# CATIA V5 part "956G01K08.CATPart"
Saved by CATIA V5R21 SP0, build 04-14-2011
Part number: 956G01K08
Bounding box of the stored display mesh (mm): x -33.75 to 33.05, y -127.5 to 127.5, z -8 to 12
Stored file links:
  C:\Users\ALI OZGUN\Desktop\alhan\TESLIMEDILEN3\956G01K08.CATPart
  C:\Users\ALI OZGUN\Desktop\alhan\TESLIMEDILEN3\960B01P01.CATPart
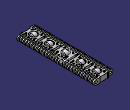
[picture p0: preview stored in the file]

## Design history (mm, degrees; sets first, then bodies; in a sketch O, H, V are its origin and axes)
Set1
  Plane1: type Normal, Curve Sketch6, RefPoint Sketch6.P3
Body1 (main body)
  Sketch1 on zx-plane, origin (0, 0, 0), H (-1, 0, 0), V (0, 0, 1)
    construction line L1 (-25.05, 0) -> (25.75, 0)
    point P1 (-25.05, 0)
    line L2 (-25.05, 8) -> (25.75, 8)
    line L3 (25.75, -8) -> (-25.05, -8)
    arc A1 centre (25.75, 0) radius 8 from (25.75, 8) to (25.75, -8) cw
    arc A2 centre (-25.05, 0) radius 8 from (-25.05, -8) to (-25.05, 8) cw
    distance L1 L2 = 8
    distance P1 V = 25.05
    length L1 = 50.8
    coincidence: P1 H
    horizontal: L1 H
    tangency: A1 L2, A2 L2, A1 L3, A2 L3
  Pad1: profile Sketch1, direction (0, 1, 0), length 127.5, mirrored extent
  Sketch2 on face of Pad1 from Sketch1.L2, origin (0, 0, 8), H (1, 0, 0), V (0, 1, 0)
    line L1 (-50.9731, -119.3) -> (-16.75, -119.3)
    line L2 (-15.75, -120.3) -> (-15.75, -122.5)
    line L3 (-16.75, -123.5) -> (-50.9731, -123.5)
    line L4 (-50.9731, -123.5) -> (-50.9731, -119.3)
    arc A1 centre (-16.75, -120.3) radius 1 from (-16.75, -119.3) to (-15.75, -120.3) cw
    arc A2 centre (-16.75, -122.5) radius 1 from (-15.75, -122.5) to (-16.75, -123.5) cw
    reference projected line E1 (-25.75, -127.5) -> (25.05, -127.5) from edge [start face of Pad1 | face of Pad1 from Sketch1.L2]
    reference projected line E2 through (-25.75, 0) direction (0, 1) from axis of face of Pad1 from Sketch1.A1
    radius A1 = 1
    radius A2 = 1 {= Sketch2.radius(A1)}
    length L4 = 4.2
    distance L3 E1 = 4
    distance L2 E2 = 10
    horizontal: L1 H, L3 H
    vertical: L2 V, L4 V
    tangency: A1 L1, A1 L2, A2 L2, A2 L3
  Pocket1: profile Sketch2, direction (0, 0, -1), length 30, mirrored extent
  RectPattern1: of Pocket1, direction 1 instances 32, spacing 8.2, along axis of face of Pad1 from Sketch1.A1
  Sketch3 on face of Pad1 from Sketch1.L2, origin (0, 0, 8), H (1, 0, 0), V (0, 1, 0)
    line L1 (50.2731, -123.4) -> (50.2731, -127.6)
    line L2 (50.2731, -127.6) -> (16.05, -127.6)
    arc A1 centre (16.0504, -126.5996) radius 1.0004 from (16.05, -127.6) to (15.05, -126.6) cw
    line L3 (15.05, -126.6) -> (15.05, -124.4)
    arc A2 centre (16.0504, -124.4004) radius 1.0004 from (15.05, -124.4) to (16.05, -123.4) cw
    line L4 (16.05, -123.4) -> (50.2731, -123.4)
    reference projected line E2 through (25.05, 0) direction (0, 1) from axis of face of Pad1 from Sketch1.A2
    reference projected line E3 (-25.75, -127.5) -> (25.05, -127.5) from edge [start face of Pad1 | face of Pad1 from Sketch1.L2]
    distance L3 E2 = 10
    distance L4 E3 = 4.1
  Pocket2: profile Sketch3, direction (0, 0, -1), length 30
  RectPattern2: of Pocket2, direction 1 instances 32, spacing 8.2, along axis of face of Pad1 from Sketch1.A2
  RemoveFace1: RemoveFaces (face of RectPattern2; face of RectPattern2)
  RemoveFace2: RemoveFaces (face of RectPattern1; face of RectPattern1; face of Pad1 from Sketch1.A1)
  Sketch4 on face of Pad1 from Sketch1.L2, origin (0, 0, 8), H (1, 0, 0), V (0, 1, 0)
    circle A1 centre (0, -101.5) radius 12
    point P1 (0, -101.5)
    point P2 (-13, -84.5)
    line L1 (-12, -84.5) -> (-7.7574, -84.5)
    line L2 (13, -85.5) -> (13, -89.7426)
    line L3 (-7.7574, -118.5) -> (-12, -118.5)
    line L4 (-13, -117.5) -> (-13, -113.2574)
    point P3 (13, -84.5)
    point P4 (13, -118.5)
    point P5 (-13, -118.5)
    reference projected line E1 (-25.75, -127.5) -> (25.05, -127.5) from edge [start face of Pad1 | face of Pad1 from Sketch1.L2]
    line L5 (7.0503, -86.2071) -> (11.2929, -90.4497)
    line L6 (-7.0503, -86.2071) -> (-11.2929, -90.4497)
    line L7 (-11.2929, -112.5503) -> (-7.0503, -116.7929)
    line L8 (7.0503, -116.7929) -> (11.2929, -112.5503)
    arc A2 centre (12, -117.5) radius 1 from (12, -118.5) to (13, -117.5) ccw
    point P6 (12, -118.5)
    arc A3 centre (-12, -117.5) radius 1 from (-12, -118.5) to (-13, -117.5) cw
    arc A4 centre (-12, -85.5) radius 1 from (-12, -84.5) to (-13, -85.5) ccw
    arc A5 centre (12, -85.5) radius 1 from (12, -84.5) to (13, -85.5) cw
    line L9 (13, -113.2574) -> (13, -117.5)
    line L10 (7.7574, -84.5) -> (12, -84.5)
    line L11 (-13, -89.7426) -> (-13, -85.5)
    line L12 (12, -118.5) -> (7.7574, -118.5)
    arc A6 centre (12, -113.2574) radius 1 from (13, -113.2574) to (11.2929, -112.5503) ccw
    arc A7 centre (7.7574, -85.5) radius 1 from (7.7574, -84.5) to (7.0503, -86.2071) ccw
    arc A8 centre (12, -89.7426) radius 1 from (11.2929, -90.4497) to (13, -89.7426) ccw
    arc A9 centre (-7.7574, -85.5) radius 1 from (-7.7574, -84.5) to (-7.0503, -86.2071) cw
    arc A10 centre (-12, -89.7426) radius 1 from (-13, -89.7426) to (-11.2929, -90.4497) ccw
    arc A11 centre (-12, -113.2574) radius 1 from (-13, -113.2574) to (-11.2929, -112.5503) cw
    arc A12 centre (-7.7574, -117.5) radius 1 from (-7.0503, -116.7929) to (-7.7574, -118.5) cw
    arc A13 centre (7.7574, -117.5) radius 1 from (7.7574, -118.5) to (7.0503, -116.7929) cw
    point P42 (-13, -72.3)
    line L13 (-12, -72.3) -> (12, -72.3)
    line L14 (13, -73.3) -> (13, -78.3)
    line L15 (12, -79.3) -> (-12, -79.3)
    line L16 (-13, -78.3) -> (-13, -73.3)
    point P43 (13, -79.3)
    point P44 (-13, -79.3)
    arc A14 centre (-12, -73.3) radius 1 from (-12, -72.3) to (-13, -73.3) ccw
    point P45 (-12, -72.3)
    point P46 (-13, -73.3)
    arc A15 centre (12, -73.3) radius 1 from (12, -72.3) to (13, -73.3) cw
    point P48 (12, -72.3)
    point P49 (13, -73.3)
    arc A16 centre (12, -78.3) radius 1 from (13, -78.3) to (12, -79.3) cw
    point P51 (13, -78.3)
    point P52 (12, -79.3)
    arc A17 centre (-12, -78.3) radius 1 from (-12, -79.3) to (-13, -78.3) cw
    point P54 (-12, -79.3)
    point P55 (-13, -78.3)
    axis line L17 (15.2688, -101.5) -> (-36.2816, -101.5)
    point P59 (-13, -130.7)
    point P60 (13, -123.7)
    point P61 (-13, -123.7)
    point P62 (-12, -130.7)
    point P63 (-13, -129.7)
    point P65 (12, -130.7)
    point P66 (13, -129.7)
    point P68 (13, -124.7)
    point P69 (12, -123.7)
    point P71 (-12, -123.7)
    point P72 (-13, -124.7)
    line L18 (-12, -130.7) -> (12, -130.7)
    line L19 (13, -129.7) -> (13, -124.7)
    line L20 (12, -123.7) -> (-12, -123.7)
    line L21 (-13, -124.7) -> (-13, -129.7)
    arc A18 centre (-12, -129.7) radius 1 from (-12, -130.7) to (-13, -129.7) cw
    arc A19 centre (12, -129.7) radius 1 from (12, -130.7) to (13, -129.7) ccw
    arc A20 centre (12, -124.7) radius 1 from (13, -124.7) to (12, -123.7) ccw
    arc A21 centre (-12, -124.7) radius 1 from (-12, -123.7) to (-13, -124.7) ccw
    radius A1 = 12
    distance L1 L3 = 34
    distance L4 V = 13
    distance P1 L1 = 17
    distance L3 E1 = 9
    angle L5 L1 = 45
    angle L6 L1 = 45
    angle L7 L3 = 45
    angle L8 L3 = 135
    radius A2 = 1
    radius A3 = 1 {= Sketch4.radius(A2)}
    distance P2 P3 = 26
    radius A4 = 1 {= Sketch4.radius(A2)}
    radius A5 = 1 {= Sketch4.radius(A2)}
    distance L8 A2 = 5
    distance L7 A3 = 5
    distance L6 A4 = 5
    distance L5 A5 = 5
    radius A6 = 1
    radius A7 = 1 {= Sketch4.radius(A6)}
    radius A8 = 1 {= Sketch4.radius(A6)}
    radius A9 = 1 {= Sketch4.radius(A6)}
    radius A10 = 1 {= Sketch4.radius(A6)}
    radius A11 = 1 {= Sketch4.radius(A6)}
    radius A12 = 1 {= Sketch4.radius(A6)}
    radius A13 = 1 {= Sketch4.radius(A6)}
    distance L1 L15 = 5.2
    distance P44 P42 = 7
    radius A14 = 1
    radius A15 = 1 {= Sketch4.radius(A14)}
    radius A16 = 1 {= Sketch4.radius(A14)}
    radius A17 = 1 {= Sketch4.radius(A14)}
    coincidence: P1 V, L3 P4, L2 P4, L3 P5, L4 P5, L1 P2, L4 P2, L1 P3, L2 P3, L2 L9, L1 L10, L4 L11, P6 L3, P42 L4, P43 L2, L13 P42, L16 P42, L14 P43, L15 P43, L15 P44, L16 P44, L17 P1
    horizontal: L1 H, L3 H, L10 H, L13 H, L15 H, L17 H
    vertical: L2 V, L4 V, L9 V, L11 V, L14 V, L16 V
    tangency: A2 L3, A2 L2, A3 L3, A3 L4, A4 L1, A4 L4, A5 L1, A5 L2, L12 A2, A6 L9, A6 L8, A7 L10, A7 L5, A8 L5, A8 L2, A9 L1, A9 L6, A10 L11, A10 L6, A11 L4, A11 L7, A12 L7, A12 L3, A13 L12, A13 L8, A14 L13, A14 L16, A15 L13, A15 L14, A16 L14, A16 L15, A17 L15, A17 L16
    symmetry: P42 P59 L17, P43 P60 L17, P44 P61 L17, P45 P62 L17, P46 P63 L17, P48 P65 L17, P49 P66 L17, P51 P68 L17, P52 P69 L17, P54 P71 L17, P55 P72 L17, L13 L18 L17, L14 L19 L17, L15 L20 L17, L16 L21 L17, A14 A18 L17, A15 A19 L17, A16 A20 L17, A17 A21 L17
  Pocket3: profile Sketch4, direction (0, 0, -1), length 30
  RectPattern3: of Pocket3, direction 1 instances 5, spacing 51.4, along axis of face of Pad1 from Sketch1.A1
  Sketch5 on face of Pocket2 from Sketch3.L4, origin (0, -123.4, 0), H (1, 0, 0), V (0, 0, 1)
    circle A1 centre (25.05, 0) radius 3.5
    reference projected arc E1 centre (25.05, 0) radius 8 from (25.05, -8) to (25.05, 8) ccw from edge [face of Pocket2 from Sketch3.L4 | face of Pad1 from Sketch1.A2]
    circle A2 centre (-25.05, 0) radius 3.5
    radius A1 = 3.5
    concentricity: A1 E1
    symmetry: A1 A2 V
  Pocket4: profile Sketch5, direction (0, 1, 0), length 321, mirrored extent
Body2
  Solid1: linked copy from another document
  Translate1: Direction yz-plane, Length 50.8, ToTransfor Solid1
Body3
  Sketch6 on xy-plane, origin (0, 0, 0), H (1, 0, 0), V (0, 1, 0)
    point P1 (0, -101.5)
    reference projected circle E1 centre (0, -101.5) radius 12 from edge [face of Pad1 from Sketch1.L2 | face of Pocket3 from Sketch4.A1]
    line L1 (-12.5, -101.5) -> (12.5, -101.5)
    point P3 (12.5, -101.5)
    length L1 = 25
    distance P3 V = 12.5
    concentricity: P1 E1
    horizontal: L1 H
    coincidence: L1 P1
  Sketch7 on Plane1, origin (12.5, 0, 0), H (0, 1, 0), V (0, 0, 1)
    circle A1 centre (-101.5, 0) radius 1.5
    point P1 (-101.5, 0)
    reference projected point E1 (-101.5, 0) from Sketch6.P3
    radius A1 = 1.5
    coincidence: P1 E1
  Slot1: profile Sketch7, centre curve Sketch6
  Translate2: Direction xy-plane, Length 4, ToTransfor Slot1
  RectPattern4: of the body so far, direction 1 instances 5, spacing 51.4, along axis of face of Pad1 from Sketch1.A2
Body4
  Sketch8 on yz-plane, origin (0, 0, 0), H (0, 1, 0), V (0, 0, 1)
    circle A1 centre (-101.5, 4) radius 8
    reference projected point E1 (-101.5, 4) from axis of face of Slot1
    circle A2 centre (-101.5, 3.7143) radius 1.75
    radius A1 = 8
    radius A2 = 1.75
    concentricity: A1 E1
  Pad2: profile Sketch8, direction (1, 0, 0), length 8, mirrored extent
  Fillet1: radius 2, on edge [face of Pad2 from Sketch8.A1 | end face of Pad2]; edge [start face of Pad2 | face of Pad2 from Sketch8.A1]
  RectPattern5: of the body so far, direction 1 instances 5, spacing 51.4, along axis of face of Pad1 from Sketch1.A2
